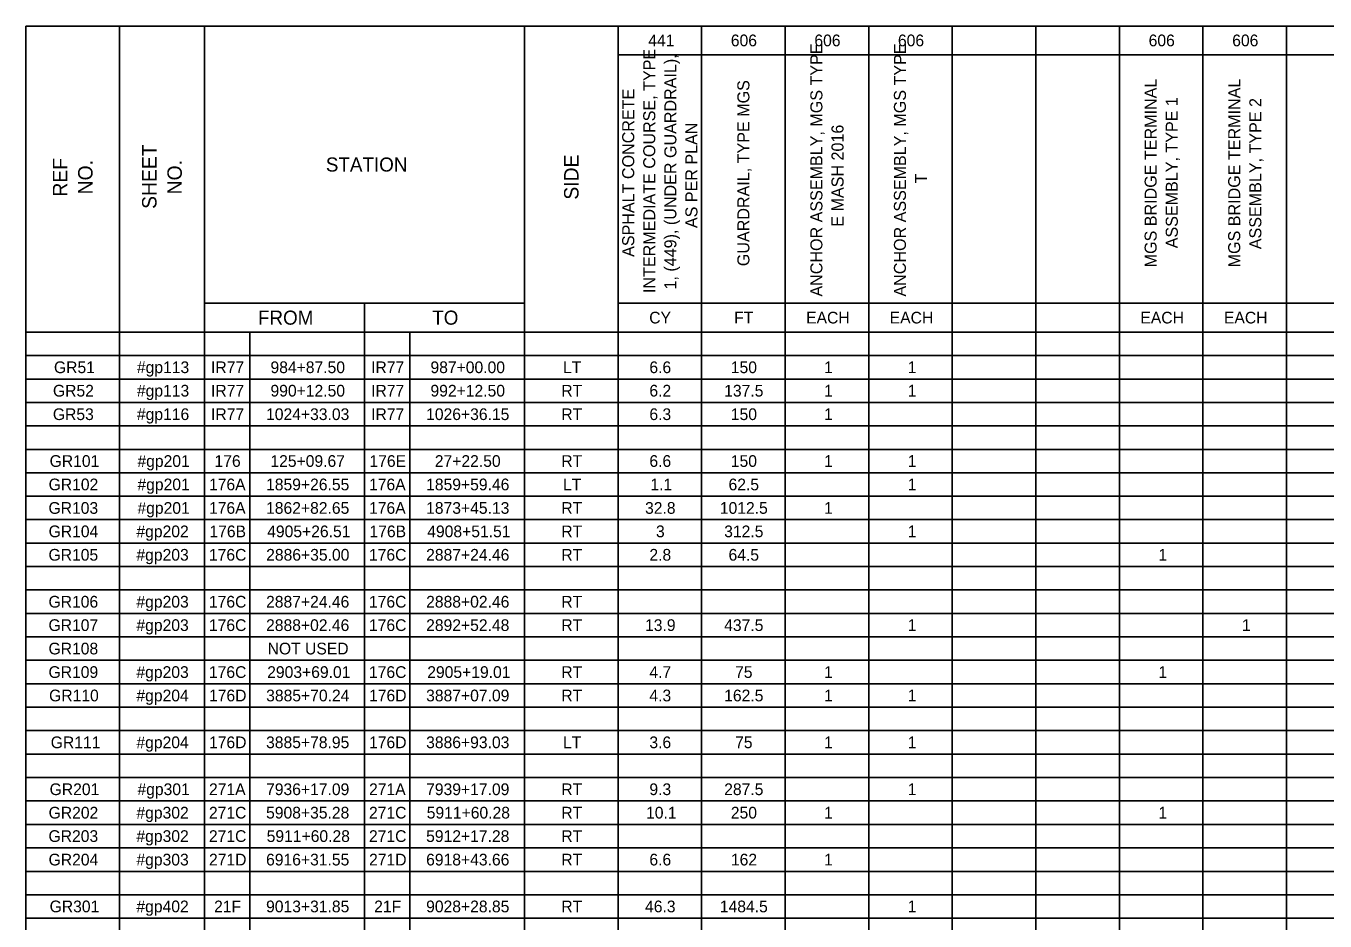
# Model space of a CAD drawing. Extents: x -542 to 295, y -281 to 32.
# Drawn here: x -16.36 to -1.11, y -120.1 to -109.59 of the extents above; entities that cross this region are included whole.
import ezdxf

# ---------------------------------------------------------------- set-up
doc = ezdxf.new("R2010")
doc.units = 0
doc.layers.add('SC_Scratch1', color=7, linetype='Continuous')
doc.layers.add('SH_Text', color=7, linetype='Continuous')

msp = doc.modelspace()

# ---------------------------------------------------------------- linework, layer by layer
at = {"layer": 'SC_Scratch1'}
msp.add_lwpolyline([(-16.359, -109.593), (14.141, -109.593), (14.141, -130.593), (-16.359, -130.593)], close=True, dxfattribs=at)
at = {"layer": 'SH_Text'}
for p, q in [((-16.359, -109.593), (14.136, -109.593)), ((-16.359, -109.593), (-16.359, -130.594)), ((-15.261, -109.593), (-15.261, -129.979)), ((-14.263, -109.593), (-14.263, -129.979)), ((-10.506, -109.593), (-10.506, -129.979)), ((-9.408, -109.593), (-9.408, -130.594)), ((-8.427, -109.593), (-8.427, -130.594)), ((-7.446, -109.593), (-7.446, -130.594)), ((-6.465, -109.593), (-6.465, -130.594)), ((-5.484, -109.593), (-5.484, -130.594)), ((-4.503, -109.593), (-4.503, -130.594)), ((-3.522, -109.593), (-3.522, -130.594)), ((-2.541, -109.593), (-2.541, -130.594)), ((-1.56, -109.593), (-1.56, -130.594)), ((-9.408, -109.933), (14.136, -109.933)), ((-14.263, -112.847), (-10.506, -112.847)), ((-12.385, -112.847), (-12.385, -129.979)), ((-9.408, -112.847), (14.136, -112.847)), ((-16.359, -113.187), (14.136, -113.187)), ((-13.731, -113.187), (-13.731, -129.979)), ((-11.852, -113.187), (-11.852, -129.979)), ((-16.359, -113.463), (14.136, -113.463)), ((-16.359, -113.738), (14.136, -113.738)), ((-16.359, -114.013), (14.136, -114.013)), ((-16.359, -114.288), (14.136, -114.288)), ((-16.359, -114.564), (14.136, -114.564)), ((-16.359, -114.839), (14.136, -114.839)), ((-16.359, -115.114), (14.136, -115.114)), ((-16.359, -115.389), (14.136, -115.389)), ((-16.359, -115.665), (14.136, -115.665)), ((-16.359, -115.94), (14.136, -115.94)), ((-16.359, -116.215), (14.136, -116.215)), ((-16.359, -116.491), (14.136, -116.491)), ((-16.359, -116.766), (14.136, -116.766)), ((-16.359, -117.041), (14.136, -117.041)), ((-16.359, -117.316), (14.136, -117.316)), ((-16.359, -117.592), (14.136, -117.592)), ((-16.359, -117.867), (14.136, -117.867)), ((-16.359, -118.142), (14.136, -118.142)), ((-16.359, -118.417), (14.136, -118.417)), ((-16.359, -118.693), (14.136, -118.693)), ((-16.359, -118.968), (14.136, -118.968)), ((-16.359, -119.243), (14.136, -119.243)), ((-16.359, -119.519), (14.136, -119.519)), ((-16.359, -119.794), (14.136, -119.794)), ((-16.359, -120.069), (14.136, -120.069))]:
    msp.add_line(p, q, dxfattribs=at)

# ---------------------------------------------------------------- texts
for s, height, p in [('441', 0.1376, (-9.053, -109.831)), ('606', 0.1376, (-8.084, -109.831)), ('606', 0.1376, (-7.103, -109.831)), ('606', 0.1376, (-6.122, -109.831)), ('606', 0.1376, (-3.179, -109.831)), ('606', 0.1376, (-2.198, -109.831)), ('STATION', 0.1652, (-12.838, -111.302)), ('FROM', 0.1652, (-13.635, -113.1)), ('TO', 0.1652, (-11.589, -113.1)), ('CY', 0.1376, (-9.042, -113.086)), ('FT', 0.1376, (-8.045, -113.086)), ('EACH', 0.1376, (-7.2, -113.086)), ('EACH', 0.1376, (-6.219, -113.086)), ('EACH', 0.1376, (-3.276, -113.086)), ('EACH', 0.1376, (-2.295, -113.086)), ('GR51', 0.1376, (-16.03, -113.669)), ('#gp113', 0.1376, (-15.056, -113.669)), ('IR77', 0.1376, (-14.186, -113.669)), ('984+87.50', 0.1376, (-13.488, -113.669)), ('IR77', 0.1376, (-12.307, -113.669)), ('987+00.00', 0.1376, (-11.61, -113.669)), ('LT', 0.1376, (-10.054, -113.669)), ('6.6', 0.1376, (-9.04, -113.669)), ('150', 0.1376, (-8.084, -113.669)), ('1', 0.138, (-6.989, -113.669)), ('1', 0.138, (-6.008, -113.669)), ('GR52', 0.1376, (-16.042, -113.944)), ('#gp113', 0.1376, (-15.056, -113.944)), ('IR77', 0.1376, (-14.186, -113.944)), ('990+12.50', 0.1376, (-13.488, -113.944)), ('IR77', 0.1376, (-12.307, -113.944)), ('992+12.50', 0.1376, (-11.61, -113.944)), ('RT', 0.1376, (-10.074, -113.944)), ('6.2', 0.1376, (-9.04, -113.944)), ('137.5', 0.1376, (-8.162, -113.944)), ('1', 0.138, (-6.989, -113.944)), ('1', 0.138, (-6.008, -113.944)), ('GR53', 0.1376, (-16.043, -114.22)), ('#gp116', 0.1376, (-15.056, -114.22)), ('IR77', 0.1376, (-14.186, -114.22)), ('1024+33.03', 0.1376, (-13.54, -114.22)), ('IR77', 0.1376, (-12.307, -114.22)), ('1026+36.15', 0.1376, (-11.661, -114.22)), ('RT', 0.1376, (-10.074, -114.22)), ('6.3', 0.1376, (-9.04, -114.22)), ('150', 0.1376, (-8.084, -114.22)), ('1', 0.138, (-6.989, -114.22)), ('GR101', 0.1376, (-16.081, -114.77)), ('#gp201', 0.1376, (-15.05, -114.77)), ('176', 0.1376, (-14.145, -114.77)), ('125+09.67', 0.1376, (-13.489, -114.77)), ('176E', 0.1376, (-12.326, -114.77)), ('27+22.50', 0.1376, (-11.559, -114.77)), ('RT', 0.1376, (-10.074, -114.77)), ('6.6', 0.1376, (-9.04, -114.77)), ('150', 0.1376, (-8.084, -114.77)), ('1', 0.138, (-6.989, -114.77)), ('1', 0.138, (-6.008, -114.77)), ('GR102', 0.1376, (-16.093, -115.045)), ('#gp201', 0.1376, (-15.05, -115.045)), ('176A', 0.1376, (-14.21, -115.045)), ('1859+26.55', 0.1376, (-13.54, -115.045)), ('176A', 0.1376, (-12.331, -115.045)), ('1859+59.46', 0.1376, (-11.661, -115.045)), ('LT', 0.1376, (-10.054, -115.045)), ('1.1', 0.1376, (-9.028, -115.045)), ('62.5', 0.1376, (-8.111, -115.045)), ('1', 0.138, (-6.008, -115.045)), ('GR103', 0.1376, (-16.094, -115.321)), ('#gp201', 0.1376, (-15.05, -115.321)), ('176A', 0.1376, (-14.21, -115.321)), ('1862+82.65', 0.1376, (-13.54, -115.321)), ('176A', 0.1376, (-12.331, -115.321)), ('1873+45.13', 0.1376, (-11.661, -115.321)), ('RT', 0.1376, (-10.074, -115.321)), ('32.8', 0.1376, (-9.091, -115.321)), ('1012.5', 0.1376, (-8.213, -115.321)), ('1', 0.138, (-6.989, -115.321)), ('GR104', 0.1376, (-16.093, -115.596)), ('#gp202', 0.1376, (-15.062, -115.596)), ('176B', 0.1376, (-14.205, -115.596)), ('4905+26.51', 0.1376, (-13.527, -115.596)), ('176B', 0.1376, (-12.326, -115.596)), ('4908+51.51', 0.1376, (-11.648, -115.596)), ('RT', 0.1376, (-10.074, -115.596)), ('3', 0.138, (-8.963, -115.596)), ('312.5', 0.1376, (-8.162, -115.596)), ('1', 0.138, (-6.008, -115.596)), ('GR105', 0.1376, (-16.094, -115.871)), ('#gp203', 0.1376, (-15.062, -115.871)), ('176C', 0.1376, (-14.211, -115.871)), ('2886+35.00', 0.1376, (-13.539, -115.871)), ('176C', 0.1376, (-12.332, -115.871)), ('2887+24.46', 0.1376, (-11.661, -115.871)), ('RT', 0.1376, (-10.074, -115.871)), ('2.8', 0.1376, (-9.04, -115.871)), ('64.5', 0.1376, (-8.111, -115.871)), ('1', 0.138, (-3.065, -115.871)), ('GR106', 0.1376, (-16.094, -116.422)), ('#gp203', 0.1376, (-15.062, -116.422)), ('176C', 0.1376, (-14.211, -116.422)), ('2887+24.46', 0.1376, (-13.54, -116.422)), ('176C', 0.1376, (-12.332, -116.422)), ('2888+02.46', 0.1376, (-11.661, -116.422)), ('RT', 0.1376, (-10.074, -116.422)), ('GR107', 0.1376, (-16.094, -116.697)), ('#gp203', 0.1376, (-15.062, -116.697)), ('176C', 0.1376, (-14.211, -116.697)), ('2888+02.46', 0.1376, (-13.54, -116.697)), ('176C', 0.1376, (-12.332, -116.697)), ('2892+52.48', 0.1376, (-11.661, -116.697)), ('RT', 0.1376, (-10.074, -116.697)), ('13.9', 0.1376, (-9.091, -116.697)), ('437.5', 0.1376, (-8.162, -116.697)), ('1', 0.138, (-6.008, -116.697)), ('1', 0.138, (-2.084, -116.697)), ('GR108', 0.1376, (-16.094, -116.972)), ('NOT USED', 0.1376, (-13.522, -116.972)), ('GR109', 0.1376, (-16.094, -117.248)), ('#gp203', 0.1376, (-15.062, -117.248)), ('176C', 0.1376, (-14.211, -117.248)), ('2903+69.01', 0.1376, (-13.527, -117.248)), ('176C', 0.1376, (-12.332, -117.248)), ('2905+19.01', 0.1376, (-11.648, -117.248)), ('RT', 0.1376, (-10.074, -117.248)), ('4.7', 0.1376, (-9.04, -117.248)), ('75', 0.1376, (-8.034, -117.248)), ('1', 0.138, (-6.989, -117.248)), ('1', 0.138, (-3.065, -117.248)), ('GR110', 0.1376, (-16.087, -117.523)), ('#gp204', 0.1376, (-15.062, -117.523)), ('176D', 0.1376, (-14.21, -117.523)), ('3885+70.24', 0.1376, (-13.539, -117.523)), ('176D', 0.1376, (-12.331, -117.523)), ('3887+07.09', 0.1376, (-11.661, -117.523)), ('RT', 0.1376, (-10.074, -117.523)), ('4.3', 0.1376, (-9.04, -117.523)), ('162.5', 0.1376, (-8.162, -117.523)), ('1', 0.138, (-6.989, -117.523)), ('1', 0.138, (-6.008, -117.523)), ('GR111', 0.1376, (-16.068, -118.073)), ('#gp204', 0.1376, (-15.062, -118.073)), ('176D', 0.1376, (-14.21, -118.073)), ('3885+78.95', 0.1376, (-13.54, -118.073)), ('176D', 0.1376, (-12.331, -118.073)), ('3886+93.03', 0.1376, (-11.661, -118.073)), ('LT', 0.1376, (-10.054, -118.073)), ('3.6', 0.1376, (-9.04, -118.073)), ('75', 0.1376, (-8.034, -118.073)), ('1', 0.138, (-6.989, -118.073)), ('1', 0.138, (-6.008, -118.073)), ('GR201', 0.1376, (-16.081, -118.624)), ('#gp301', 0.1376, (-15.05, -118.624)), ('271A', 0.1376, (-14.21, -118.624)), ('7936+17.09', 0.1376, (-13.54, -118.624)), ('271A', 0.1376, (-12.331, -118.624)), ('7939+17.09', 0.1376, (-11.661, -118.624)), ('RT', 0.1376, (-10.074, -118.624)), ('9.3', 0.1376, (-9.04, -118.624)), ('287.5', 0.1376, (-8.162, -118.624)), ('1', 0.138, (-6.008, -118.624)), ('GR202', 0.1376, (-16.093, -118.899)), ('#gp302', 0.1376, (-15.062, -118.899)), ('271C', 0.1376, (-14.211, -118.899)), ('5908+35.28', 0.1376, (-13.54, -118.899)), ('271C', 0.1376, (-12.332, -118.899)), ('5911+60.28', 0.1376, (-11.654, -118.899)), ('RT', 0.1376, (-10.074, -118.899)), ('10.1', 0.1376, (-9.079, -118.899)), ('250', 0.1376, (-8.084, -118.899)), ('1', 0.138, (-6.989, -118.899)), ('1', 0.138, (-3.065, -118.899)), ('GR203', 0.1376, (-16.094, -119.174)), ('#gp302', 0.1376, (-15.062, -119.174)), ('271C', 0.1376, (-14.211, -119.174)), ('5911+60.28', 0.1376, (-13.533, -119.174)), ('271C', 0.1376, (-12.332, -119.174)), ('5912+17.28', 0.1376, (-11.661, -119.174)), ('RT', 0.1376, (-10.074, -119.174)), ('GR204', 0.1376, (-16.093, -119.45)), ('#gp303', 0.1376, (-15.062, -119.45)), ('271D', 0.1376, (-14.21, -119.45)), ('6916+31.55', 0.1376, (-13.54, -119.45)), ('271D', 0.1376, (-12.331, -119.45)), ('6918+43.66', 0.1376, (-11.661, -119.45)), ('RT', 0.1376, (-10.074, -119.45)), ('6.6', 0.1376, (-9.04, -119.45)), ('162', 0.1376, (-8.083, -119.45)), ('1', 0.138, (-6.989, -119.45)), ('GR301', 0.1376, (-16.081, -120)), ('#gp402', 0.1376, (-15.062, -120)), ('21F', 0.1376, (-14.15, -120)), ('9013+31.85', 0.1376, (-13.54, -120)), ('21F', 0.1376, (-12.271, -120)), ('9028+28.85', 0.1376, (-11.661, -120)), ('RT', 0.1376, (-10.074, -120)), ('46.3', 0.1376, (-9.091, -120)), ('1484.5', 0.1376, (-8.213, -120)), ('1', 0.138, (-6.008, -120))]:
    msp.add_text(s, height=height, dxfattribs=at).set_placement(p)
for s, height, p in [('INTERMEDIATE COURSE, TYPE ', 0.14133, (-8.971, -112.728)), ('1, (449), (UNDER GUARDRAIL), ', 0.14133, (-8.723, -112.687)), ('ANCHOR ASSEMBLY, MGS TYPE ', 0.14133, (-7.009, -112.77)), ('ANCHOR ASSEMBLY, MGS TYPE ', 0.14133, (-6.028, -112.77)), ('GUARDRAIL, TYPE MGS', 0.14133, (-7.866, -112.413)), ('MGS BRIDGE TERMINAL ', 0.14133, (-3.085, -112.427)), ('MGS BRIDGE TERMINAL ', 0.14133, (-2.104, -112.427)), ('ASPHALT CONCRETE ', 0.14133, (-9.218, -112.304)), ('ASSEMBLY, TYPE 1', 0.14133, (-2.837, -112.203)), ('ASSEMBLY, TYPE 2', 0.14133, (-1.856, -112.214)), ('AS PER PLAN', 0.14133, (-8.476, -111.966)), ('E MASH 2016', 0.14133, (-6.761, -111.949)), ('SHEET', 0.1696, (-14.826, -111.74)), ('REF', 0.1696, (-15.873, -111.596)), ('SIDE', 0.1696, (-9.872, -111.632)), ('NO.', 0.1696, (-15.577, -111.57)), ('NO.', 0.1696, (-14.529, -111.57)), ('T', 0.141, (-5.78, -111.441))]:
    msp.add_text(s, height=height, rotation=90, dxfattribs=at).set_placement(p)

doc.saveas('drawing.dxf')
